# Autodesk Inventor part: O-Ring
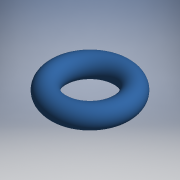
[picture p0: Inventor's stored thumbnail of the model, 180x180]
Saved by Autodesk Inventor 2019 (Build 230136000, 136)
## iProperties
Shininess: 50.0
Compacted: True
Length Units: 11272
Angle Units: 11279
Time Units: 11290
Mass Units: 11286
Length Display Precision: 4
Angle Display Precision: 2
Company: Autodesk
Created: 2000-03
Part Number: O-Ring
Project: Inventor Samples
User Status: IN PROGRESS
Document SubType Name: Modeling
Designer: Autodesk, Inc.
Density: 0.93 g/cm^3
Mass: 0.0275413 g
Surface Area: 0.746188 cm^2
Volume: 0.0296144 cm^3
Material: Rubber
Appearance: Sky Blue
Density: 0.0
Volumn: 0.0
Area: 0.0
PropertySet Name: Model Information
Control State: 0
Master: False
Checked Out: False
Checked Out Date: 2018-05-30
Last Check In Date: 2018-05-30
Author: Autodesk, Inc.
Revision Number: A
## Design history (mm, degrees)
node "Revolution1" dims "d4" = 90 deg
  sketch "Sketch2"
    geometry: L1 (-2.997, -11.455)-(-2.997, -15.497); A1 r 0.794 centre (-0.616, -13.252) between (0.178, -13.252) and (-1.409, -13.252); 2 further points
    constraints: 4 point on circle, 2 end point, 2 horizontal alignment, 2 vertical alignment, 1 centre point, 1 vertical
    dimensions: "d2" = 6.35 diameter of A1.start L1; "d3" = 3.175 diameter of A1.end L1
workplane "Work Plane1"
workplane "Work Plane2"
workaxis "Work Axis1"
body "Solid1"
